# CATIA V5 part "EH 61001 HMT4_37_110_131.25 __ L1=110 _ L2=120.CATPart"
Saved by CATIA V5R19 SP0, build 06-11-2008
Definition: EH 61001 HMT4_37_110_131.25 __ L1=110 _ L2=120
Nomenclature: EH 61001 HMT4_37_110_131.25 __ L1=110 _ L2=120
Description: PART--DESC
Material "Steel": density 7860 kg/m3, Young's modulus 2e+11 Pa, Poisson ratio 0.266, thermal expansion 1.17e-05 1/K
Bounding box of the stored display mesh (mm): x -176.5 to 176.5, y -160 to 160, z 35.25 to 92.75
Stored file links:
  G:\UTB\Kombinované\Bakalářská práce\Catia\FORMA\EH 61001 HMT4_37_110_131.25 __ L1=110 _ L2=120.CATPart
  D:\Aplikace\CATIA\Nová složka\win_b64\startup\materials\Catalog.CATMaterial
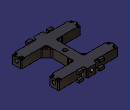
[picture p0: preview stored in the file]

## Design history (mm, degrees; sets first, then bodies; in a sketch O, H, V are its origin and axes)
Body1 (main body)
  Solid1 "EH 61001 HMT4_37_110_131.25 __ L1=110 _ L2=120": solid without history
